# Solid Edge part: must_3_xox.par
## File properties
Author: Romil
Template: iso part.par
Last saved by: Romil
Revision: 43
Application: Solid Edge
Accuracy: 0.990
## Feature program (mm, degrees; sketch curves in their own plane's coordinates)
sketch for "unnamed Protrusion 1" plane through (0, 0, 0) normal (1, 0, 0) x-axis (0, 1, 0)
  line (-0.25, -3.6) -> (-7.75, -3.6)
  line (-7.75, -3.6) -> (-8, -3.6)
  arc centre (-8, 0) radius 3.6 from (-8, 3.6) to (-8, -3.6) ccw
  line (-7.75, 3.6) -> (-8, 3.6)
  line (-0.25, 3.6) -> (-7.75, 3.6)
  line (0.25, 3.6) -> (-0.25, 3.6)
  line (0.25, 3.6) -> (7.75, 3.6)
  line (7.75, 3.6) -> (8, 3.6)
  arc centre (8, 0) radius 3.6 from (8, 3.6) to (8, -3.6) cw
  line (7.75, -3.6) -> (8, -3.6)
  line (0.25, -3.6) -> (7.75, -3.6)
  line (-0.25, -3.6) -> (0.25, -3.6)
extrude "unnamed Protrusion 1" add finite 3.8 symmetric
sketch for "unnamed Cutout 1" #1 plane through (0, 0, 0) normal (1, 0, 0) x-axis (0, 1, 0)
  line (-7.125, 0.975) -> (-7.125, 2.0449)
  line (-7.125, 2.0449) -> (-7.125, 2.181)
  arc centre (-8, 0) radius 2.35 from (-7.125, 2.181) to (-8.875, 2.181) ccw
  line (-8.875, 2.181) -> (-8.875, 2.0449)
  line (-8.875, 2.0449) -> (-8.875, 0.975)
  arc centre (-8.975, 0.975) radius 0.1 from (-8.875, 0.975) to (-8.975, 0.875) cw
  line (-8.975, 0.875) -> (-10.0449, 0.875)
  line (-10.0449, 0.875) -> (-10.181, 0.875)
  arc centre (-8, 0) radius 2.35 from (-10.181, 0.875) to (-10.181, -0.875) ccw
  line (-10.181, -0.875) -> (-10.0449, -0.875)
  line (-10.0449, -0.875) -> (-8.975, -0.875)
  arc centre (-8.975, -0.975) radius 0.1 from (-8.975, -0.875) to (-8.875, -0.975) cw
  line (-8.875, -0.975) -> (-8.875, -2.0449)
  line (-8.875, -2.0449) -> (-8.875, -2.181)
  arc centre (-8, 0) radius 2.35 from (-8.875, -2.181) to (-7.125, -2.181) ccw
  line (-7.125, -2.181) -> (-7.125, -2.0449)
  line (-7.125, -2.0449) -> (-7.125, -0.975)
  arc centre (-7.025, -0.975) radius 0.1 from (-7.125, -0.975) to (-7.025, -0.875) cw
  line (-7.025, -0.875) -> (-5.9551, -0.875)
  line (-5.9551, -0.875) -> (-4.9163, -0.875)
  arc centre (-4.9163, -1.175) radius 0.3 from (-4.6359, -1.2818) to (-4.9163, -0.875) ccw
  arc centre (-8, 0) radius 3.6 from (-4.6359, -1.2818) to (-5.2216, -2.2892) cw
  arc centre (-4.9901, -2.48) radius 0.3 from (-5.2216, -2.2892) to (-4.9901, -2.78) ccw
  line (-4.9901, -2.78) -> (-2.9696, -2.78)
  arc centre (-2.9696, -2.48) radius 0.3 from (-2.9696, -2.78) to (-2.7381, -2.2892) ccw
  arc centre (0.0403, 0) radius 3.6 from (-2.7381, -2.2892) to (-2.7381, 2.2892) cw
  arc centre (-2.9696, 2.48) radius 0.3 from (-2.7381, 2.2892) to (-2.9696, 2.78) ccw
  line (-4.9901, 2.78) -> (-2.9696, 2.78)
  arc centre (-4.9901, 2.48) radius 0.3 from (-4.9901, 2.78) to (-5.2216, 2.2892) ccw
  arc centre (-8, 0) radius 3.6 from (-5.2216, 2.2892) to (-4.6359, 1.2818) cw
  arc centre (-4.9163, 1.175) radius 0.3 from (-4.9163, 0.875) to (-4.6359, 1.2818) ccw
  line (-4.9163, 0.875) -> (-5.9551, 0.875)
  line (-5.9551, 0.875) -> (-7.025, 0.875)
  arc centre (-7.025, 0.975) radius 0.1 from (-7.025, 0.875) to (-7.125, 0.975) cw
sketch for "unnamed Cutout 1" #2 plane through (0, 0, 0) normal (1, 0, 0) x-axis (0, 1, 0)
sketch for "unnamed Cutout 1" #3 plane through (0, 0, 0) normal (1, 0, 0) x-axis (0, 1, 0)
  circle centre (0, 0) radius 2.4
extrude "unnamed Cutout 1" cut finite 115.7809 symmetric
sketch for "ExtrudedCutout_37" plane through (1.9, 0, 0) normal (1, 0, 0) x-axis (0, 1, 0)
  circle centre (0, 0) radius 3.1
extrude "ExtrudedCutout_37" cut finite 0.9 along -normal
mirror "unnamed Mirror 1" of "ExtrudedCutout_37" about plane through (0, 0, 0) normal (1, 0, 0)
extrude "unnamed Cutout 2" cut finite 0.9
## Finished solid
Body 1: solid body, 63 faces, 174 edges, 112 vertices.
  Faces by surface: cylinder 37, plane 26
  Edges by curve: line 100, circle 74
Bounding box of the edges (mm): 3.800 x 23.200 x 7.200, from (-1.9, -11.6, -3.6) to (1.9, 11.6, 3.6).
Cylindrical faces by radius (mm): R0.1 x8, R0.3 x12, R2.35 x6, R2.4 x1, R3.1 x2, R3.6 x8
Planar faces by outward normal: +x 2, +y 4, +z 7, -x 2, -y 4, -z 7
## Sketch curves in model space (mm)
circle centre (1.9, 0, 0) radius 3.1
circle centre (0, 0, 0) radius 2.4
circle centre (0, 0, 0) radius 3.1
arc centre (0, -8.975, 0.975) radius 0.1 from (0, -8.875, 0.975) through (0, -8.9064, 0.9023) to (0, -8.975, 0.875)
line (0, -8.975, 0.875) -> (0, -10.0449, 0.875)
line (0, -10.0449, 0.875) -> (0, -10.181, 0.875)
arc centre (0, -8, 0) radius 2.35 from (0, -10.181, 0.875) through (0, -10.35, 0) to (0, -10.181, -0.875)
line (0, -10.181, -0.875) -> (0, -10.0449, -0.875)
line (0, -10.0449, -0.875) -> (0, -8.975, -0.875)
arc centre (0, -8.975, -0.975) radius 0.1 from (0, -8.975, -0.875) through (0, -8.9023, -0.9064) to (0, -8.875, -0.975)
line (0, -8.875, -0.975) -> (0, -8.875, -2.0449)
line (0, -8.875, -2.0449) -> (0, -8.875, -2.181)
arc centre (0, -8, 0) radius 2.35 from (0, -8.875, -2.181) through (0, -8, -2.35) to (0, -7.125, -2.181)
line (0, -7.125, -2.181) -> (0, -7.125, -2.0449)
line (0, -7.125, -2.0449) -> (0, -7.125, -0.975)
arc centre (0, -7.025, -0.975) radius 0.1 from (0, -7.125, -0.975) through (0, -7.0936, -0.9023) to (0, -7.025, -0.875)
line (0, -7.025, -0.875) -> (0, -5.9551, -0.875)
line (0, -5.9551, -0.875) -> (0, -4.9163, -0.875)
arc centre (0, -4.9163, -1.175) radius 0.3 from (0, -4.6359, -1.2818) through (0, -4.6743, -0.9976) to (0, -4.9163, -0.875)
arc centre (0, -8, 0) radius 3.6 from (0, -4.6359, -1.2818) through (0, -4.8877, -1.8094) to (0, -5.2216, -2.2892)
arc centre (0, -4.9901, -2.48) radius 0.3 from (0, -5.2216, -2.2892) through (0, -5.2614, -2.608) to (0, -4.9901, -2.78)
line (0, -4.9901, -2.78) -> (0, -2.9696, -2.78)
arc centre (0, -2.9696, -2.48) radius 0.3 from (0, -2.9696, -2.78) through (0, -2.6983, -2.608) to (0, -2.7381, -2.2892)
arc centre (0, 0.0403, 0) radius 3.6 from (0, -2.7381, -2.2892) through (0, -3.5581, 0.1079) to (0, -2.7381, 2.2892)
arc centre (0, -2.9696, 2.48) radius 0.3 from (0, -2.7381, 2.2892) through (0, -2.6983, 2.608) to (0, -2.9696, 2.78)
line (0, -4.9901, 2.78) -> (0, -2.9696, 2.78)
arc centre (0, -4.9901, 2.48) radius 0.3 from (0, -4.9901, 2.78) through (0, -5.2614, 2.608) to (0, -5.2216, 2.2892)
arc centre (0, -8, 0) radius 3.6 from (0, -5.2216, 2.2892) through (0, -4.8877, 1.8094) to (0, -4.6359, 1.2818)
arc centre (0, -4.9163, 1.175) radius 0.3 from (0, -4.9163, 0.875) through (0, -4.6644, 1.0121) to (0, -4.6359, 1.2818)
line (0, -4.9163, 0.875) -> (0, -5.9551, 0.875)
line (0, -5.9551, 0.875) -> (0, -7.025, 0.875)
arc centre (0, -7.025, 0.975) radius 0.1 from (0, -7.025, 0.875) through (0, -7.0977, 0.9064) to (0, -7.125, 0.975)
line (0, -7.125, 0.975) -> (0, -7.125, 2.0449)
line (0, -7.125, 2.0449) -> (0, -7.125, 2.181)
arc centre (0, -8, 0) radius 2.35 from (0, -7.125, 2.181) through (0, -8, 2.35) to (0, -8.875, 2.181)
line (0, -8.875, 2.181) -> (0, -8.875, 2.0449)
line (0, -8.875, 2.0449) -> (0, -8.875, 0.975)
line (0, -7.75, -3.6) -> (0, -8, -3.6)
line (0, -0.25, -3.6) -> (0, -7.75, -3.6)
line (0, -0.25, -3.6) -> (0, 0.25, -3.6)
line (0, 0.25, -3.6) -> (0, 7.75, -3.6)
line (0, 7.75, -3.6) -> (0, 8, -3.6)
arc centre (0, 8, 0) radius 3.6 from (0, 8, 3.6) through (0, 11.5984, -0.1067) to (0, 8, -3.6)
line (0, 7.75, 3.6) -> (0, 8, 3.6)
line (0, 0.25, 3.6) -> (0, 7.75, 3.6)
line (0, 0.25, 3.6) -> (0, -0.25, 3.6)
line (0, -0.25, 3.6) -> (0, -7.75, 3.6)
line (0, -7.75, 3.6) -> (0, -8, 3.6)
arc centre (0, -8, 0) radius 3.6 from (0, -8, 3.6) through (0, -11.5984, -0.1067) to (0, -8, -3.6)
arc centre (0, 8.975, 0.975) radius 0.1 from (0, 8.875, 0.975) through (0, 8.9064, 0.9023) to (0, 8.975, 0.875)
line (0, 8.975, 0.875) -> (0, 10.0449, 0.875)
line (0, 10.0449, 0.875) -> (0, 10.181, 0.875)
arc centre (0, 8, 0) radius 2.35 from (0, 10.181, 0.875) through (0, 10.35, 0) to (0, 10.181, -0.875)
line (0, 10.181, -0.875) -> (0, 10.0449, -0.875)
line (0, 10.0449, -0.875) -> (0, 8.975, -0.875)
arc centre (0, 8.975, -0.975) radius 0.1 from (0, 8.975, -0.875) through (0, 8.9023, -0.9064) to (0, 8.875, -0.975)
line (0, 8.875, -0.975) -> (0, 8.875, -2.0449)
line (0, 8.875, -2.0449) -> (0, 8.875, -2.181)
arc centre (0, 8, 0) radius 2.35 from (0, 8.875, -2.181) through (0, 8, -2.35) to (0, 7.125, -2.181)
line (0, 7.125, -2.181) -> (0, 7.125, -2.0449)
line (0, 7.125, -2.0449) -> (0, 7.125, -0.975)
arc centre (0, 7.025, -0.975) radius 0.1 from (0, 7.125, -0.975) through (0, 7.0936, -0.9023) to (0, 7.025, -0.875)
line (0, 7.025, -0.875) -> (0, 5.9551, -0.875)
line (0, 5.9551, -0.875) -> (0, 4.9163, -0.875)
arc centre (0, 4.9163, -1.175) radius 0.3 from (0, 4.6359, -1.2818) through (0, 4.6743, -0.9976) to (0, 4.9163, -0.875)
arc centre (0, 8, 0) radius 3.6 from (0, 4.6359, -1.2818) through (0, 4.8877, -1.8094) to (0, 5.2216, -2.2892)
arc centre (0, 4.9901, -2.48) radius 0.3 from (0, 5.2216, -2.2892) through (0, 5.2614, -2.608) to (0, 4.9901, -2.78)
line (0, 4.9901, -2.78) -> (0, 2.9696, -2.78)
arc centre (0, 2.9696, -2.48) radius 0.3 from (0, 2.9696, -2.78) through (0, 2.6983, -2.608) to (0, 2.7381, -2.2892)
arc centre (0, -0.0403, 0) radius 3.6 from (0, 2.7381, -2.2892) through (0, 3.5581, 0.1079) to (0, 2.7381, 2.2892)
arc centre (0, 2.9696, 2.48) radius 0.3 from (0, 2.7381, 2.2892) through (0, 2.6983, 2.608) to (0, 2.9696, 2.78)
line (0, 4.9901, 2.78) -> (0, 2.9696, 2.78)
arc centre (0, 4.9901, 2.48) radius 0.3 from (0, 4.9901, 2.78) through (0, 5.2614, 2.608) to (0, 5.2216, 2.2892)
arc centre (0, 8, 0) radius 3.6 from (0, 5.2216, 2.2892) through (0, 4.8877, 1.8094) to (0, 4.6359, 1.2818)
arc centre (0, 4.9163, 1.175) radius 0.3 from (0, 4.9163, 0.875) through (0, 4.6644, 1.0121) to (0, 4.6359, 1.2818)
line (0, 4.9163, 0.875) -> (0, 5.9551, 0.875)
line (0, 5.9551, 0.875) -> (0, 7.025, 0.875)
arc centre (0, 7.025, 0.975) radius 0.1 from (0, 7.025, 0.875) through (0, 7.0977, 0.9064) to (0, 7.125, 0.975)
line (0, 7.125, 0.975) -> (0, 7.125, 2.0449)
line (0, 7.125, 2.0449) -> (0, 7.125, 2.181)
arc centre (0, 8, 0) radius 2.35 from (0, 7.125, 2.181) through (0, 8, 2.35) to (0, 8.875, 2.181)
line (0, 8.875, 2.181) -> (0, 8.875, 2.0449)
line (0, 8.875, 2.0449) -> (0, 8.875, 0.975)
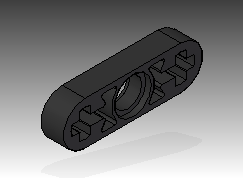
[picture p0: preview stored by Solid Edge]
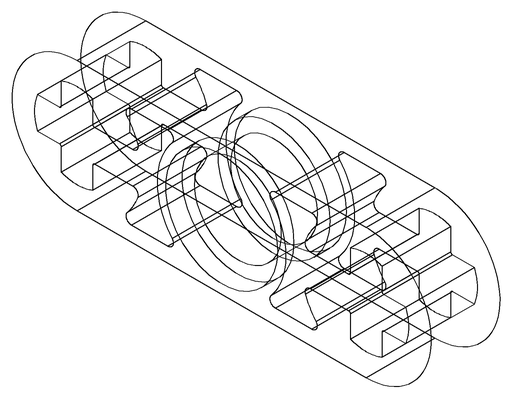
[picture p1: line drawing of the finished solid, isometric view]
